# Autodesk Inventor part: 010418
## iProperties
Shininess: 60.0
Length Units: 11269
Angle Units: 11279
Time Units: 11290
Mass Units: 11283
Length Display Precision: 3
Angle Display Precision: 2
Compacted: True
Company: Pneumax S.p.A.
Part Number: 010418
Description: RACCORDO DIRITTO G1/8 Ø4
Document SubType Name: Modellazione
Catalog Web Link: www.pneumaxspa.com
Density: 0.0
Volumn: 0.0
Area: 0.0
PropertySet Name: Model Information
Control State: 0
Master: False
Checked Out: False
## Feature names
1. Rivoluzione1 [Revolution]
2. Revolution3
3. Estrusione1 [Extrusion]
4. Serie circolare1 [Circular Pattern]
5. Smusso3 [Chamfer]
6. Foro1 [Hole]
